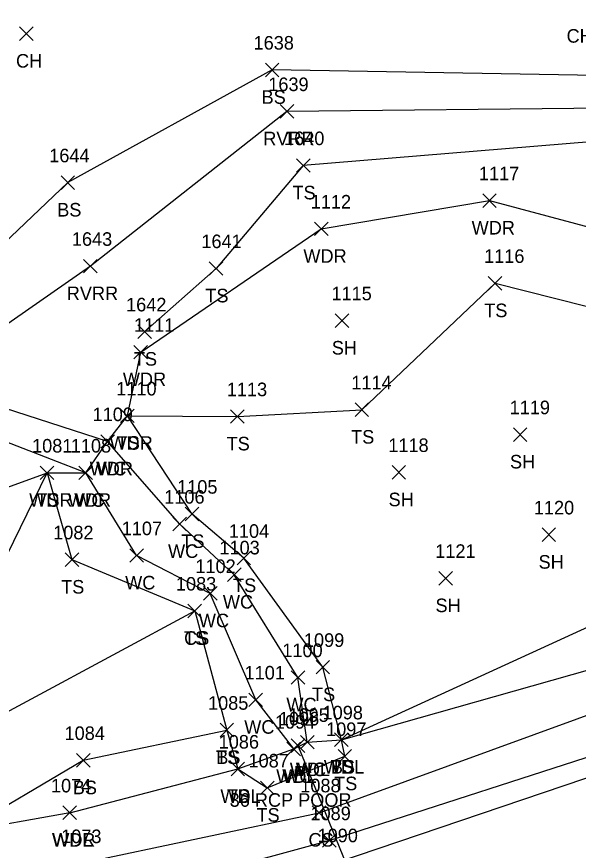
# Model space of a CAD drawing. Extents: x 1443064 to 1445163, y 544063 to 544655.
# Drawn here: x 1443153.5 to 1443236.3, y 544151.7 to 544274.6 of the extents above; entities that cross this region are included whole.
import ezdxf

# ---------------------------------------------------------------- set-up
doc = ezdxf.new("R2010")
doc.units = 0
for name, color, linetype in [('D_A', 7, 'Continuous'), ('D_C', 7, 'Continuous'), ('D_I', 7, 'Continuous'), ('D_TIC', 7, 'Continuous'), ('DCP', 7, 'Continuous'), ('L_A', 7, 'Continuous'), ('L_I', 7, 'Continuous'), ('L_TIC', 7, 'Continuous'), ('LAWA', 7, 'Continuous'), ('LAWE', 7, 'Continuous'), ('LELB', 7, 'Continuous'), ('P_I', 7, 'Continuous'), ('PET', 7, 'Continuous')]:
    doc.layers.add(name, color=color, linetype=linetype)

msp = doc.modelspace()

# ---------------------------------------------------------------- linework, layer by layer
at = {"layer": 'D_TIC'}
for points in [[(1443193.97, 544166.11), (1443195.97, 544168.11)], [(1443195.97, 544166.11), (1443193.97, 544168.11)]]:
    msp.add_lwpolyline(points, dxfattribs=at)
at = {"layer": 'DCP'}
msp.add_lwpolyline([(1443216.42, 544114.54), (1443194.97, 544167.11)], dxfattribs=at)
at = {"layer": 'L_TIC'}
for points in [[(1443153.87, 544271.11), (1443155.87, 544273.11)], [(1443155.87, 544271.11), (1443153.87, 544273.11)], [(1443190.15, 544265.77), (1443192.15, 544267.77)], [(1443192.15, 544265.77), (1443190.15, 544267.77)], [(1443192.33, 544259.65), (1443194.33, 544261.65)], [(1443194.33, 544259.65), (1443192.33, 544261.65)], [(1443194.74, 544251.68), (1443196.74, 544253.68)], [(1443196.74, 544251.68), (1443194.74, 544253.68)], [(1443160, 544249.15), (1443162, 544251.15)], [(1443162, 544249.15), (1443160, 544251.15)], [(1443222.22, 544246.5), (1443224.22, 544248.5)], [(1443224.22, 544246.5), (1443222.22, 544248.5)], [(1443197.4, 544242.33), (1443199.4, 544244.33)], [(1443199.4, 544242.33), (1443197.4, 544244.33)], [(1443163.34, 544236.83), (1443165.34, 544238.83)], [(1443165.34, 544236.83), (1443163.34, 544238.83)], [(1443181.88, 544236.49), (1443183.88, 544238.49)], [(1443183.88, 544236.49), (1443181.88, 544238.49)], [(1443223.03, 544234.31), (1443225.03, 544236.31)], [(1443225.03, 544234.31), (1443223.03, 544236.31)], [(1443200.46, 544228.8), (1443202.46, 544230.8)], [(1443202.46, 544228.8), (1443200.46, 544230.8)], [(1443171.34, 544227.16), (1443173.34, 544229.16)], [(1443173.34, 544227.16), (1443171.34, 544229.16)], [(1443170.76, 544224.15), (1443172.76, 544226.15)], [(1443172.76, 544224.15), (1443170.76, 544226.15)], [(1443203.39, 544215.66), (1443205.39, 544217.66)], [(1443205.39, 544215.66), (1443203.39, 544217.66)], [(1443168.79, 544214.76), (1443170.79, 544216.76)], [(1443170.79, 544214.76), (1443168.79, 544216.76)], [(1443168.79, 544214.76), (1443170.79, 544216.76)], [(1443170.79, 544214.76), (1443168.79, 544216.76)], [(1443185.02, 544214.66), (1443187.02, 544216.66)], [(1443187.02, 544214.66), (1443185.02, 544216.66)], [(1443226.75, 544212), (1443228.75, 544214)], [(1443228.75, 544212), (1443226.75, 544214)], [(1443165.87, 544210.98), (1443167.87, 544212.98)], [(1443167.87, 544210.98), (1443165.87, 544212.98)], [(1443165.87, 544210.98), (1443167.87, 544212.98)], [(1443167.87, 544210.98), (1443165.87, 544212.98)], [(1443156.94, 544206.35), (1443158.94, 544208.35)], [(1443158.94, 544206.35), (1443156.94, 544208.35)], [(1443156.94, 544206.35), (1443158.94, 544208.35)], [(1443158.94, 544206.35), (1443156.94, 544208.35)], [(1443162.64, 544206.35), (1443164.64, 544208.35)], [(1443164.64, 544206.35), (1443162.64, 544208.35)], [(1443162.64, 544206.35), (1443164.64, 544208.35)], [(1443164.64, 544206.35), (1443162.64, 544208.35)], [(1443208.84, 544206.43), (1443210.84, 544208.43)], [(1443210.84, 544206.43), (1443208.84, 544208.43)], [(1443178.33, 544200.28), (1443180.33, 544202.28)], [(1443180.33, 544200.28), (1443178.33, 544202.28)], [(1443176.49, 544198.81), (1443178.49, 544200.81)], [(1443178.49, 544198.81), (1443176.49, 544200.81)], [(1443230.97, 544197.22), (1443232.97, 544199.22)], [(1443232.97, 544197.22), (1443230.97, 544199.22)], [(1443160.61, 544193.55), (1443162.61, 544195.55)], [(1443162.61, 544193.55), (1443160.61, 544195.55)], [(1443170.16, 544194.16), (1443172.16, 544196.16)], [(1443172.16, 544194.16), (1443170.16, 544196.16)], [(1443185.97, 544193.77), (1443187.97, 544195.77)], [(1443187.97, 544193.77), (1443185.97, 544195.77)], [(1443184.57, 544191.33), (1443186.57, 544193.33)], [(1443186.57, 544191.33), (1443184.57, 544193.33)], [(1443215.76, 544190.81), (1443217.76, 544192.81)], [(1443217.76, 544190.81), (1443215.76, 544192.81)], [(1443181.02, 544188.58), (1443183.02, 544190.58)], [(1443183.02, 544188.58), (1443181.02, 544190.58)], [(1443178.72, 544185.99), (1443180.72, 544187.99)], [(1443180.72, 544185.99), (1443178.72, 544187.99)], [(1443178.72, 544185.99), (1443180.72, 544187.99)], [(1443180.72, 544185.99), (1443178.72, 544187.99)], [(1443197.62, 544177.69), (1443199.62, 544179.69)], [(1443199.62, 544177.69), (1443197.62, 544179.69)], [(1443193.95, 544176.18), (1443195.95, 544178.18)], [(1443195.95, 544176.18), (1443193.95, 544178.18)], [(1443187.72, 544172.88), (1443189.72, 544174.88)], [(1443189.72, 544172.88), (1443187.72, 544174.88)], [(1443183.46, 544168.42), (1443185.46, 544170.42)], [(1443185.46, 544168.42), (1443183.46, 544170.42)], [(1443183.46, 544168.42), (1443185.46, 544170.42)], [(1443185.46, 544168.42), (1443183.46, 544170.42)], [(1443195.33, 544166.63), (1443197.33, 544168.63)], [(1443197.33, 544166.63), (1443195.33, 544168.63)], [(1443195.33, 544166.63), (1443197.33, 544168.63)], [(1443197.33, 544166.63), (1443195.33, 544168.63)], [(1443200.36, 544167), (1443202.36, 544169)], [(1443202.36, 544167), (1443200.36, 544169)], [(1443200.36, 544167), (1443202.36, 544169)], [(1443202.36, 544167), (1443200.36, 544169)], [(1443200.36, 544167), (1443202.36, 544169)], [(1443202.36, 544167), (1443200.36, 544169)], [(1443193.34, 544165.63), (1443195.34, 544167.63)], [(1443195.34, 544165.63), (1443193.34, 544167.63)], [(1443193.34, 544165.63), (1443195.34, 544167.63)], [(1443195.34, 544165.63), (1443193.34, 544167.63)], [(1443162.29, 544163.96), (1443164.29, 544165.96)], [(1443164.29, 544163.96), (1443162.29, 544165.96)], [(1443200.88, 544164.55), (1443202.88, 544166.55)], [(1443202.88, 544164.55), (1443200.88, 544166.55)], [(1443185.09, 544162.69), (1443187.09, 544164.69)], [(1443187.09, 544162.69), (1443185.09, 544164.69)], [(1443185.09, 544162.69), (1443187.09, 544164.69)], [(1443187.09, 544162.69), (1443185.09, 544164.69)], [(1443189.43, 544159.91), (1443191.43, 544161.91)], [(1443191.43, 544159.91), (1443189.43, 544161.91)], [(1443160.29, 544156.23), (1443162.29, 544158.23)], [(1443162.29, 544156.23), (1443160.29, 544158.23)], [(1443160.29, 544156.23), (1443162.29, 544158.23)], [(1443162.29, 544156.23), (1443160.29, 544158.23)], [(1443197.07, 544156.24), (1443199.07, 544158.24)], [(1443199.07, 544156.24), (1443197.07, 544158.24)], [(1443198.58, 544152.13), (1443200.58, 544154.13)], [(1443200.58, 544152.13), (1443198.58, 544154.13)]]:
    msp.add_lwpolyline(points, dxfattribs=at)
at = {"layer": 'LAWA'}
for points in [[(1443161.29, 544157.23), (1443186.09, 544163.69), (1443194.34, 544166.63), (1443196.33, 544167.63), (1443201.36, 544168), (1443240.97, 544179.17), (1443262.42, 544188.86), (1443303.08, 544207.19), (1443347.02, 544222.79), (1443391.79, 544240.14), (1443432.68, 544254.71), (1443466.61, 544275.19), (1443493.21, 544282.75), (1443512.25, 544287.37), (1443549.07, 544304.36), (1443598.9, 544317.54), (1443643.36, 544329.59), (1443677.18, 544341.83), (1443688.03, 544341.71), (1443709.45, 544338.47), (1443741.32, 544354.61), (1443794.32, 544372.46), (1443818.98, 544380.86)], [(1443161.29, 544157.23), (1443145.28, 544154.36), (1443143.53, 544167.56), (1443146.04, 544183.08), (1443157.94, 544207.35), (1443163.64, 544207.35), (1443166.87, 544211.98), (1443169.79, 544215.76), (1443171.76, 544225.15), (1443198.4, 544243.33), (1443223.22, 544247.5), (1443248.61, 544240.73), (1443289.53, 544254.52), (1443328.33, 544272.01), (1443354.38, 544286)]]:
    msp.add_lwpolyline(points, dxfattribs=at)
at = {"layer": 'LAWE'}
for points in [[(1443627.73, 544516.96), (1443602.93, 544465.06), (1443560.09, 544445.87), (1443514.11, 544419.1), (1443476.33, 544389.4), (1443439.4, 544357.75), (1443402.97, 544339.11), (1443368.14, 544318.06), (1443323.16, 544292.42), (1443281.44, 544273.46), (1443240.37, 544261.14), (1443193.33, 544260.65), (1443164.34, 544237.83), (1443139.78, 544220.74), (1443138.28, 544217.17), (1443133.77, 544210.32), (1443100.97, 544202.05)], [(1443196.33, 544167.63), (1443194.95, 544177.18), (1443185.57, 544192.33), (1443177.49, 544199.81), (1443166.87, 544211.98), (1443139.78, 544220.74)], [(1443194.34, 544166.63), (1443188.72, 544173.88), (1443182.02, 544189.58), (1443171.16, 544195.16), (1443163.64, 544207.35), (1443138.28, 544217.17)]]:
    msp.add_lwpolyline(points, dxfattribs=at)
at = {"layer": 'LELB'}
for points in [[(1443623.25, 544521.72), (1443599.67, 544467.52), (1443557.8, 544451.16), (1443512.32, 544424.47), (1443473.97, 544391.39), (1443436.99, 544360.77), (1443402.58, 544340.48), (1443365.21, 544324.82), (1443319.81, 544300.23), (1443279.76, 544280.29), (1443239.01, 544265.94), (1443191.15, 544266.77), (1443161, 544250.15), (1443130.5, 544221.16), (1443098.72, 544215.41)], [(1443630.6, 544513.66), (1443606.19, 544459.79), (1443563.47, 544440.26), (1443516.58, 544414.23), (1443479.57, 544386.27), (1443441.49, 544354.15), (1443406.03, 544333.57), (1443372.48, 544309.35), (1443326.54, 544284.19), (1443284.74, 544264.48), (1443242.9, 544256.57), (1443195.74, 544252.68), (1443182.88, 544237.49), (1443172.34, 544228.16)], [(1443073.59, 544128.34), (1443116.66, 544141.89), (1443162.8, 544149.75), (1443198.07, 544157.24), (1443242.5, 544173.41), (1443262.84, 544182.05), (1443307.11, 544199.46), (1443348.85, 544214.35), (1443394.74, 544233.02), (1443435.02, 544243.93), (1443473.16, 544259.47), (1443514.32, 544272.16), (1443555.56, 544285.54), (1443605.06, 544302.52), (1443644.56, 544313.72), (1443676.09, 544324.26), (1443689.45, 544326.75), (1443708.55, 544330.01), (1443714.07, 544333.45), (1443742.84, 544349.83), (1443793.92, 544368.99), (1443822.61, 544377.56)], [(1443074.67, 544122.4), (1443120.32, 544131.74), (1443165.11, 544143.77), (1443199.58, 544153.13), (1443245.24, 544167.88), (1443264.59, 544177.57), (1443308.86, 544194.48), (1443350.56, 544209.36), (1443397.32, 544225.82), (1443437.1, 544238.98), (1443476.53, 544253.14), (1443516.75, 544265.8), (1443558.95, 544280.95), (1443607.52, 544296.39), (1443646.45, 544306.32), (1443685.12, 544319.06), (1443714.26, 544329.16), (1443721.31, 544331.26), (1443744.28, 544345.57), (1443795.65, 544366.53), (1443822.61, 544377.56)], [(1443065.69, 544181.55), (1443109.31, 544188.89), (1443136.73, 544199.63), (1443157.94, 544207.35), (1443161.61, 544194.55), (1443179.72, 544186.99), (1443184.46, 544169.42), (1443186.09, 544163.69), (1443190.43, 544160.91), (1443201.88, 544165.55), (1443201.36, 544168), (1443198.62, 544178.69), (1443186.97, 544194.77), (1443179.33, 544201.28), (1443169.79, 544215.76), (1443186.02, 544215.66), (1443204.39, 544216.66), (1443224.03, 544235.31), (1443250.92, 544228.56), (1443292.51, 544245.42), (1443354.38, 544286)], [(1443201.36, 544168), (1443239.03, 544185.22), (1443261.77, 544197.6), (1443298.3, 544219.12), (1443343.36, 544234.64)], [(1443069.8, 544145.63), (1443114.86, 544159.03), (1443143.53, 544167.56), (1443179.72, 544186.99)], [(1443071.73, 544136.06), (1443116.84, 544147.19), (1443145.28, 544154.36), (1443163.29, 544164.96), (1443184.46, 544169.42)]]:
    msp.add_lwpolyline(points, dxfattribs=at)
at = {"layer": 'PET'}
msp.add_lwpolyline([(1443075.39, 544117.71), (1443121.41, 544129.24), (1443165.99, 544140.07), (1443200.71, 544149.88), (1443246.42, 544165.39), (1443265.96, 544172.48), (1443311.2, 544187.88), (1443352.92, 544202.76), (1443399.28, 544220.13), (1443438.78, 544233.67), (1443478.75, 544247.35), (1443518.41, 544260.6), (1443561.23, 544274.05), (1443611.7, 544290.5), (1443646.84, 544301.68), (1443684.98, 544314.55), (1443724.57, 544327.54), (1443735.41, 544331.22), (1443748.81, 544336.36), (1443799.43, 544353.96), (1443827.31, 544364.14)], dxfattribs=at)

# ---------------------------------------------------------------- texts
at = {"layer": 'D_A'}
msp.add_text('P', height=2, dxfattribs=at).set_placement((1443194.35, 544162.11))
at = {"layer": 'D_C'}
msp.add_text('36 RCP POOR', height=2, dxfattribs=at).set_placement((1443184.88, 544158.11))
at = {"layer": 'D_I'}
msp.add_text('1096', height=2, dxfattribs=at).set_placement((1443192.14, 544170.11))
at = {"layer": 'L_A'}
for s, p in [('CH', (1443234.59, 544270.79)), ('CH', (1443153.36, 544267.11)), ('BS', (1443189.59, 544261.77)), ('RVRR', (1443189.84, 544255.65)), ('TS', (1443194.15, 544247.68)), ('BS', (1443159.44, 544245.15)), ('WDR', (1443220.58, 544242.5)), ('WDR', (1443195.76, 544238.33)), ('RVRR', (1443160.85, 544232.83)), ('TS', (1443181.29, 544232.49)), ('TS', (1443222.44, 544230.31)), ('SH', (1443199.95, 544224.8)), ('TS', (1443170.75, 544223.16)), ('WDR', (1443169.12, 544220.15)), ('WDR', (1443167.15, 544210.76)), ('TS', (1443168.2, 544210.76)), ('TS', (1443184.43, 544210.66)), ('TS', (1443202.8, 544211.66)), ('WDR', (1443164.23, 544206.98)), ('WC', (1443165.18, 544206.98)), ('SH', (1443226.24, 544208)), ('WDR', (1443155.3, 544202.35)), ('TS', (1443156.35, 544202.35)), ('WDR', (1443161.01, 544202.35)), ('WC', (1443161.95, 544202.35)), ('SH', (1443208.33, 544202.43)), ('TS', (1443177.74, 544196.28)), ('WC', (1443175.79, 544194.81)), ('SH', (1443230.46, 544193.22)), ('WC', (1443169.46, 544190.16)), ('TS', (1443185.38, 544189.77)), ('TS', (1443160.02, 544189.55)), ('WC', (1443183.88, 544187.33)), ('SH', (1443215.25, 544186.81)), ('WC', (1443180.33, 544184.58)), ('TS', (1443178.13, 544181.99)), ('CS', (1443178.16, 544181.99)), ('TS', (1443197.03, 544173.69)), ('WC', (1443193.25, 544172.18)), ('WC', (1443187.03, 544168.88)), ('TS', (1443182.87, 544164.42)), ('BS', (1443182.9, 544164.42)), ('WDL', (1443193.75, 544162.63)), ('WC', (1443194.64, 544162.63)), ('WDL', (1443198.78, 544163)), ('TS', (1443199.77, 544163)), ('BS', (1443199.81, 544163)), ('WDL', (1443191.75, 544161.63)), ('WC', (1443192.64, 544161.63)), ('TS', (1443200.29, 544160.55)), ('BS', (1443161.73, 544159.96)), ('WDL', (1443183.51, 544158.69)), ('TS', (1443184.5, 544158.69)), ('TS', (1443188.84, 544155.91)), ('WDR', (1443158.66, 544152.23)), ('WDL', (1443158.71, 544152.23)), ('CS', (1443196.51, 544152.24))]:
    msp.add_text(s, height=2, dxfattribs=at).set_placement(p)
at = {"layer": 'L_I'}
for s, p in [('1638', (1443188.41, 544269.77)), ('1639', (1443190.58, 544263.65)), ('1640', (1443192.91, 544255.68)), ('1644', (1443158.26, 544253.15)), ('1117', (1443221.66, 544250.5)), ('1112', (1443196.84, 544246.33)), ('1643', (1443161.6, 544240.83)), ('1641', (1443180.71, 544240.49)), ('1116', (1443222.42, 544238.31)), ('1115', (1443199.9, 544232.8)), ('1642', (1443169.6, 544231.16)), ('1111', (1443170.77, 544228.15)), ('1114', (1443202.83, 544219.66)), ('1110', (1443168.15, 544218.76)), ('1110', (1443168.15, 544218.76)), ('1113', (1443184.46, 544218.66)), ('1119', (1443226.19, 544216)), ('1109', (1443164.66, 544214.98)), ('1109', (1443164.66, 544214.98)), ('1081', (1443155.73, 544210.35)), ('1081', (1443155.73, 544210.35)), ('1108', (1443161.44, 544210.35)), ('1108', (1443161.44, 544210.35)), ('1118', (1443208.29, 544210.43)), ('1105', (1443177.13, 544204.28)), ('1106', (1443175.23, 544202.81)), ('1120', (1443229.76, 544201.22)), ('1082', (1443158.84, 544197.55)), ('1107', (1443168.95, 544198.16)), ('1104', (1443184.76, 544197.77)), ('1103', (1443183.37, 544195.33)), ('1121', (1443215.21, 544194.81)), ('1102', (1443179.82, 544192.58)), ('1083', (1443176.95, 544189.99)), ('1083', (1443176.95, 544189.99)), ('1099', (1443195.84, 544181.69)), ('1100', (1443192.65, 544180.18)), ('1101', (1443187.08, 544176.88)), ('1085', (1443181.69, 544172.42)), ('1085', (1443181.69, 544172.42)), ('1095', (1443193.56, 544170.63)), ('1095', (1443193.56, 544170.63)), ('1098', (1443198.59, 544171)), ('1098', (1443198.59, 544171)), ('1098', (1443198.59, 544171)), ('1094', (1443191.56, 544169.63)), ('1094', (1443191.56, 544169.63)), ('1084', (1443160.52, 544167.96)), ('1097', (1443199.11, 544168.55)), ('1086', (1443183.26, 544166.69)), ('1086', (1443183.26, 544166.69)), ('1087', (1443187.66, 544163.91)), ('1074', (1443158.52, 544160.23)), ('1074', (1443158.52, 544160.23)), ('1088', (1443195.3, 544160.24)), ('1089', (1443196.8, 544156.13)), ('1073', (1443160.02, 544152.75))]:
    msp.add_text(s, height=2, dxfattribs=at).set_placement(p)
at = {"layer": 'P_I'}
msp.add_text('1090', height=2, dxfattribs=at).set_placement((1443197.85, 544152.88))

doc.saveas('drawing.dxf')
